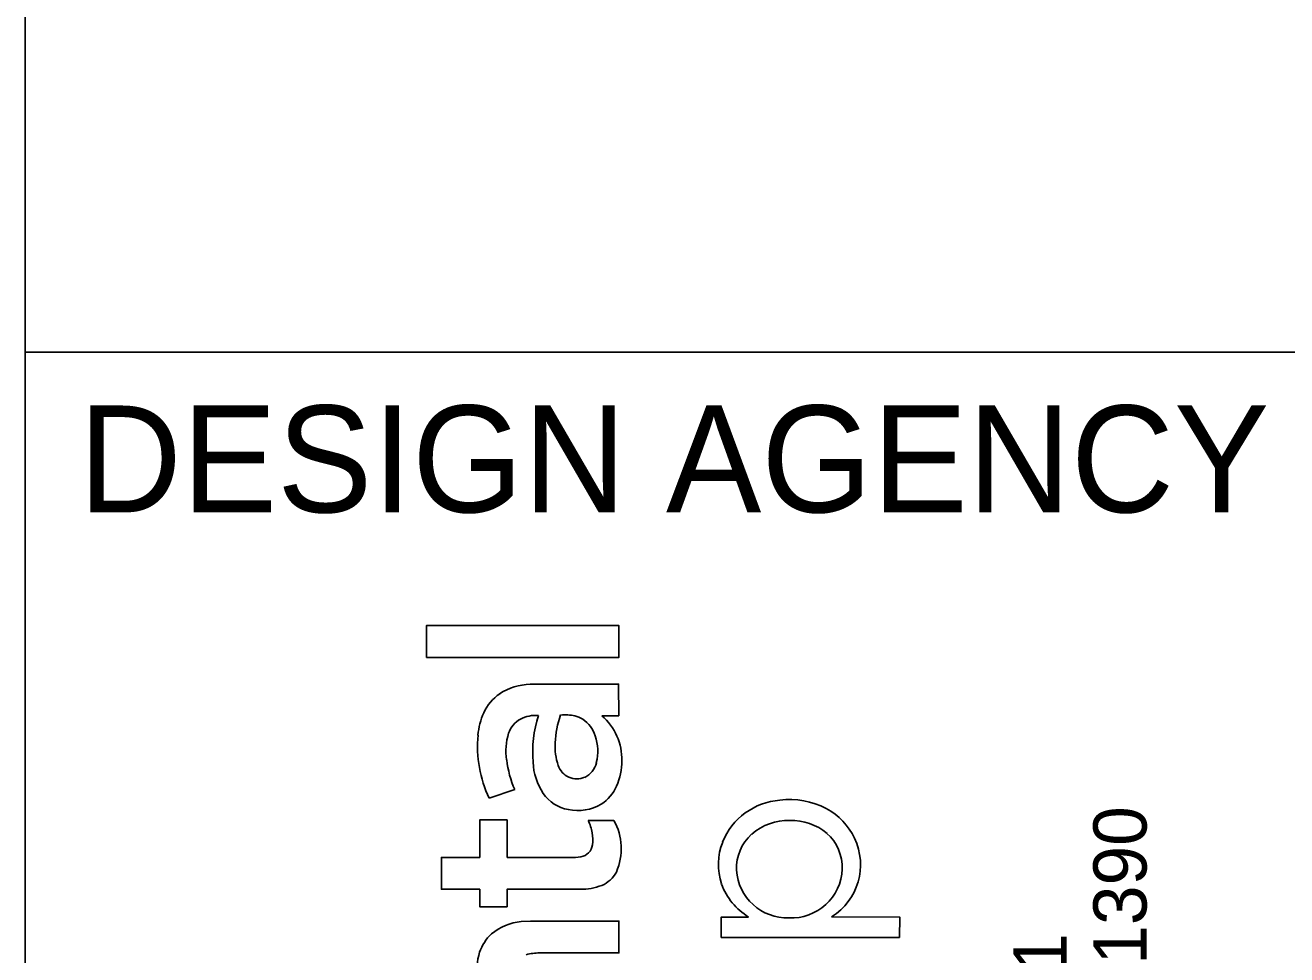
# Model space of a CAD drawing. Extents: x -4.4 to 34, y 0 to 22.
# Drawn here: x 32 to 33.181, y 3.936 to 4.806 of the extents above; entities that cross this region are included whole.
import ezdxf

# ---------------------------------------------------------------- set-up
doc = ezdxf.new("R2010")
doc.units = 0
doc.layers.add('PF_X_Ground_Line', color=7, linetype='Continuous')
doc.layers.add('UT_X_FO', color=7, linetype='Continuous')

msp = doc.modelspace()

# ---------------------------------------------------------------- linework, layer by layer
at = {"layer": 'PF_X_Ground_Line'}
for p, q in [((32.3756, 4.2141), (32.3756, 4.244)), ((32.3756, 4.244), (32.5557, 4.244)), ((32.5557, 4.244), (32.5557, 4.2141)), ((32.5557, 4.2141), (32.3756, 4.2141)), ((32.4727, 4.189), (32.5555, 4.1892)), ((32.5555, 4.1892), (32.5557, 4.1596)), ((32.5557, 4.1596), (32.5397, 4.1596)), ((32.4582, 4.0904), (32.4343, 4.0823)), ((32.4254, 4.027), (32.4255, 4.0621)), ((32.4255, 4.0621), (32.4511, 4.0621)), ((32.4511, 4.0621), (32.4512, 4.027)), ((32.527, 4.0616), (32.5511, 4.0616)), ((32.3896, 3.9972), (32.3896, 4.027)), ((32.3896, 4.027), (32.4254, 4.027)), ((32.4512, 4.027), (32.515, 4.027)), ((32.515, 4.027), (32.52, 4.0275)), ((32.4254, 3.9972), (32.3896, 3.9972)), ((32.4254, 3.9807), (32.4254, 3.9972)), ((32.5197, 3.9972), (32.4511, 3.9972)), ((32.4511, 3.9972), (32.4511, 3.9807)), ((32.4511, 3.9807), (32.4254, 3.9807)), ((32.6515, 3.9521), (32.6515, 3.9711)), ((32.6515, 3.9711), (32.6771, 3.9711)), ((32.7549, 3.9713), (32.8186, 3.9711)), ((32.8186, 3.9711), (32.8184, 3.9521)), ((32.4644, 3.9669), (32.4729, 3.9673)), ((32.4729, 3.9673), (32.5557, 3.9673)), ((32.5557, 3.9673), (32.5557, 3.9375)), ((32.8184, 3.9521), (32.6515, 3.9521)), ((32.5557, 3.9375), (32.4814, 3.9375))]:
    msp.add_line(p, q, dxfattribs=at)
msp.add_lwpolyline([(32.3756, 4.2141), (32.3756, 4.244), (32.5557, 4.244), (32.5557, 4.2141)], close=True, dxfattribs=at)
for points in [[(32.4727, 4.189), (32.5555, 4.1892), (32.5557, 4.1596)], [(32.5557, 4.1596), (32.5397, 4.1596)], [(32.4582, 4.0904), (32.4343, 4.0823)], [(32.5197, 3.9972), (32.4511, 3.9972), (32.4511, 3.9807), (32.4254, 3.9807), (32.4254, 3.9972), (32.3896, 3.9972), (32.3896, 4.027), (32.4254, 4.027), (32.4255, 4.0621), (32.4511, 4.0621), (32.4512, 4.027), (32.515, 4.027), (32.52, 4.0275)], [(32.527, 4.0616), (32.5511, 4.0616)], [(32.7549, 3.9713), (32.8186, 3.9711), (32.8184, 3.9521), (32.6515, 3.9521)], [(32.6515, 3.9521), (32.6515, 3.9711), (32.6771, 3.9711)], [(32.4644, 3.9669), (32.4729, 3.9673), (32.5557, 3.9673), (32.5557, 3.9375), (32.4814, 3.9375)]]:
    msp.add_lwpolyline(points, dxfattribs=at)
for centre, radius, start, end in [((32.4745, 4.1326), 0.0565, 91.8942, 122.6317), ((32.4745, 4.1326), 0.0565, 91.8942, 122.6317), ((32.4685, 4.1447), 0.043, 124.537, 155.6594), ((32.4685, 4.1447), 0.043, 124.537, 155.6594), ((32.4882, 4.1361), 0.0646, 155.9764, 175.3149), ((32.4882, 4.1361), 0.0646, 155.9764, 175.3149), ((32.4779, 4.1278), 0.0321, 85.3802, 116.6222), ((32.4779, 4.1278), 0.0321, 85.3802, 116.6222), ((32.5879, 4.1251), 0.1129, 162.0821, 184.5285), ((32.5879, 4.1251), 0.1129, 162.0821, 184.5285), ((32.5801, 4.1313), 0.0841, 159.8366, 178.0362), ((32.5801, 4.1313), 0.0841, 159.8366, 178.0362), ((32.5051, 4.1074), 0.053, 79.6696, 94.2322), ((32.5051, 4.1074), 0.053, 79.6696, 94.2322), ((32.5089, 4.1364), 0.0238, 56.8913, 76.2149), ((32.5089, 4.1364), 0.0238, 56.8913, 76.2149), ((32.5055, 4.1191), 0.0529, 358.0746, 49.762), ((32.5055, 4.1191), 0.0529, 358.0746, 49.762), ((32.4753, 4.1356), 0.024, 119.4252, 161.6629), ((32.4753, 4.1356), 0.024, 119.4252, 161.6629), ((32.5052, 4.1318), 0.0297, 17.5984, 55.7282), ((32.5052, 4.1318), 0.0297, 17.5984, 55.7282), ((32.5364, 4.1308), 0.113, 174.6101, 205.3899), ((32.5364, 4.1308), 0.113, 174.6101, 205.3899), ((32.5076, 4.1265), 0.0576, 163.1369, 188.1675), ((32.5076, 4.1265), 0.0576, 163.1369, 188.1675), ((32.5466, 4.1303), 0.0506, 175.5903, 199.8857), ((32.5466, 4.1303), 0.0506, 175.5903, 199.8857), ((32.4916, 4.1264), 0.0443, 345.9408, 18.9919), ((32.4916, 4.1264), 0.0443, 345.9408, 18.9919), ((32.5473, 4.1297), 0.0973, 186.7598, 203.7981), ((32.5473, 4.1297), 0.0973, 186.7598, 203.7981), ((32.5328, 4.1187), 0.0575, 182.5676, 213.7144), ((32.5328, 4.1187), 0.0575, 182.5676, 213.7144), ((32.5164, 4.1189), 0.0184, 198.2844, 293.3081), ((32.5164, 4.1189), 0.0184, 198.2844, 293.3081), ((32.5152, 4.1199), 0.0199, 295.2883, 347.4639), ((32.5152, 4.1199), 0.0199, 295.2883, 347.4639), ((32.5019, 4.1168), 0.0566, 336.016, 0.5951), ((32.5019, 4.1168), 0.0566, 336.016, 0.5951), ((32.5149, 4.1078), 0.0366, 215.0668, 259.8133), ((32.5149, 4.1078), 0.0366, 215.0668, 259.8133), ((32.5175, 4.1097), 0.0394, 303.4436, 336.18), ((32.5175, 4.1097), 0.0394, 303.4436, 336.18), ((32.5175, 4.1131), 0.0423, 257.5256, 300.882), ((32.5175, 4.1131), 0.0423, 257.5256, 300.882), ((32.7108, 4.0182), 0.0624, 93.9866, 158.3119), ((32.7108, 4.0182), 0.0624, 93.9866, 158.3119), ((32.7156, 4.0065), 0.0746, 62.6889, 97.0135), ((32.7156, 4.0065), 0.0746, 62.6889, 97.0135), ((32.7212, 4.0191), 0.0608, 25.0657, 61.9602), ((32.7212, 4.0191), 0.0608, 25.0657, 61.9602), ((32.4863, 4.042), 0.0452, 10.1545, 25.723), ((32.4863, 4.042), 0.0452, 10.1545, 25.723), ((32.503, 4.0351), 0.0549, 336.589, 28.8991), ((32.503, 4.0351), 0.0549, 336.589, 28.8991), ((32.7138, 4.0102), 0.0513, 87.8965, 131.1812), ((32.7138, 4.0102), 0.0513, 87.8965, 131.1812), ((32.7175, 4.0102), 0.0513, 49.9089, 92.0363), ((32.7175, 4.0102), 0.0513, 49.9089, 92.0363), ((32.4957, 4.0436), 0.0356, 351.914, 10.2059), ((32.4957, 4.0436), 0.0356, 351.914, 10.2059), ((32.707, 4.0202), 0.0581, 158.656, 198.171), ((32.707, 4.0202), 0.0581, 158.656, 198.171), ((32.7092, 4.0167), 0.0434, 132.3289, 182.0949), ((32.7092, 4.0167), 0.0434, 132.3289, 182.0949), ((32.7215, 4.0173), 0.0433, 358.0487, 47.9447), ((32.7215, 4.0173), 0.0433, 358.0487, 47.9447), ((32.7245, 4.02), 0.0574, 301.9776, 25.6418), ((32.7245, 4.02), 0.0574, 301.9776, 25.6418), ((32.5184, 4.04), 0.0126, 277.6142, 353.7918), ((32.5184, 4.04), 0.0126, 277.6142, 353.7918), ((32.7135, 4.0181), 0.0478, 183.5974, 271.7045), ((32.7135, 4.0181), 0.0478, 183.5974, 271.7045), ((32.7172, 4.018), 0.0477, 267.3149, 357.4019), ((32.7172, 4.018), 0.0477, 267.3149, 357.4019), ((32.5291, 4.0261), 0.0275, 292.6889, 332.0598), ((32.5291, 4.0261), 0.0275, 292.6889, 332.0598), ((32.5209, 4.0486), 0.0514, 268.6727, 291.5235), ((32.5209, 4.0486), 0.0514, 268.6727, 291.5235), ((32.7103, 4.0243), 0.0627, 200.8399, 238.0162), ((32.7103, 4.0243), 0.0627, 200.8399, 238.0162), ((32.4687, 3.9172), 0.0499, 94.9706, 130.2248), ((32.4687, 3.9172), 0.0499, 94.9706, 130.2248), ((32.4635, 3.9255), 0.0402, 132.2238, 161.6823), ((32.4635, 3.9255), 0.0402, 132.2238, 161.6823), ((32.4787, 3.9211), 0.056, 162.274, 187.7917), ((32.4787, 3.9211), 0.056, 162.274, 187.7917), ((32.4811, 3.8915), 0.046, 89.6051, 105.3303), ((32.4811, 3.8915), 0.046, 89.6051, 105.3303)]:
    msp.add_arc(centre, radius, start, end, dxfattribs=at)
at = {"layer": 'UT_X_FO'}
for p, q in [((32, 0.5), (32, 21.5)), ((32, 4.5), (33.5, 4.5))]:
    msp.add_line(p, q, dxfattribs=at)

# ---------------------------------------------------------------- texts
at = {"layer": 'PF_X_Ground_Line'}
msp.add_text('DESIGN AGENCY', height=0.1, dxfattribs=at).set_placement((32.05, 4.35))
for s, p in [('800.835.1390', (33.0497, 3.6671)), ('450 GRANT ST., AKRON, OH  44311', (32.9749, 2.8374))]:
    msp.add_text(s, height=0.049846, rotation=90, dxfattribs=at).set_placement(p)

doc.saveas('drawing.dxf')
